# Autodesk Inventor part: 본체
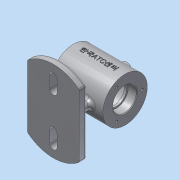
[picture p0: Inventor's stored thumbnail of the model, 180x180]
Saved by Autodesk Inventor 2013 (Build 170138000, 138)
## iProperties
Created: 2017-12
Part Number: 본체
Material: 알루미늄 6061
Document SubType Name: Modeling
Designer: dgall
Density: 2.71 g/cm^3
Mass: 467.692 g
Surface Area: 486.473 cm^2
Volume: 172.58 cm^3
Author: dgall
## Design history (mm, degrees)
sketch "스케치1"
  geometry: L1 (0, 0)-(70, 0); L2 (0, 0)-(0, 30); L3 (0, 30)-(70, 30); L4 (70, 30)-(70, 0)
  constraints: 8 end point, 2 perpendicular, 1 horizontal, 1 parallel
  dimensions: "d0" = 70 distance of L1.start L1.end; "d1" = 60 diameter of L3 L1
revolve "회전1" sketch "스케치1" stored, may be unused: angle "d2" = 90 deg
node "작업 평면1"
sketch "스케치2"
  geometry: L1 (70, -30)-(70, 30) reference; L2 (0, -30)-(0, 30) reference; L3 (0, 30)-(70, 30) reference; L4 (0, -30)-(70, -30) reference; L5 (0, 42.426)-(0, -42.426); L6 (70, 42.426)-(70, -42.426); A1 r 55 centre (35, 0) between (70, 42.426) and (0, 42.426); A2 r 55 centre (35, 0) between (0, -42.426) and (70, -42.426); 3 further points
  constraints: 4 end point, 4 point on circle, 2 centre point, 2 horizontal alignment, 2 midpoint, 1 collinear, 1 concentric, 1 parallel, 1 vertical alignment
  dimensions: "d6" = 70 distance between parallel lines of L6 L5; "d7" = 55 radius of A1
extrude "돌출1" join sketch "스케치2" distance "d8" = 10; taper "d9" = 0 deg
sketch "스케치3"
  geometry: L1 (0, 42.426)-(0, -42.426) reference; L2 (70, -42.426)-(70, 42.426) reference; L3 (20, 5)-(50, 5); L4 (50, -5)-(20, -5); A1 r 55 centre (35, 0) between (0, -42.426) and (70, -42.426) reference; A2 r 5 centre (20, 0) between (20, 5) and (20, -5); A3 r 5 centre (50, 0) between (50, -5) and (50, 5); 4 further points
  constraints: 4 end point, 4 point on circle, 4 vertical alignment, 2 centre point, 2 midpoint, 1 coincident, 1 equal radius, 1 horizontal alignment, 1 parallel, 1 perpendicular
  dimensions: "d13" = 30 distance of A3.centre point (20, 0); "d14" = 5 radius of A3
extrude "돌출2" join sketch "스케치3" stored distance "d15" = 10; taper "d16" = 0 deg
node "작업 평면2"
sketch "스케치4"
  geometry: C1 r 8 at (-35, 0); 1 further point
  constraints: 1 centre point, 1 horizontal alignment
  dimensions: "d18" = 16 diameter of C1; "d20" = 35 distance of point (0, 0) C1.centre
extrude "돌출3" join sketch "스케치4" stored distance "d21" = 10; taper "d22" = 0 deg
hole "구멍1" diameter "d25" = 28; stored, may be unused: countersink angle "d29" = 90 deg, drill point angle "d31" = 0 deg; dims "d23" = 10, "d24" = 10, "d26" = 6, "d27" = 32, "d28" = 12, "d30" = 15
hole "구멍2" diameter "d34" = 28; stored, may be unused: countersink angle "d38" = 90 deg, drill point angle "d40" = 0 deg; dims "d32" = 10, "d33" = 10, "d35" = 6, "d36" = 32, "d37" = 12, "d39" = 15
hole "구멍3" diameter "d43" = 50; stored, may be unused: countersink angle "d47" = 90 deg, drill point angle "d49" = 0 deg; dims "d41" = 10, "d42" = 10, "d44" = 6, "d45" = 32, "d46" = 12, "d48" = 40
hole "구멍4" diameter "d52" = 8; stored, may be unused: countersink angle "d56" = 90 deg, drill point angle "d58" = 0 deg; dims "d50" = 10, "d51" = 10, "d53" = 6, "d54" = 32, "d55" = 12, "d57" = 20
chamfer "모따기1" distance "d59" = 1; stored, may be unused: second distance "d60" = 2, angle "d61" = 45 deg
chamfer "모따기2" distance "d62" = 1; stored, may be unused: second distance "d63" = 2, angle "d64" = 45 deg
fillet "모깎기1" dims "d65" = 0.3
fillet "모깎기2" dims "d66" = 3
sketch "스케치5"
  geometry: L1 (40, 40)-(40, 24); L2 (30, 24)-(30, 40); A1 r 55 centre (35, 0) between (0, -42.426) and (70, -42.426) reference; A2 r 5 centre (50, 0) between (50, -5) and (50, 5) reference; A3 r 5 centre (35, 24) between (30, 24) and (40, 24); A4 r 5 centre (35, 40) between (40, 40) and (30, 40); 3 further points
  constraints: 4 end point, 4 point on circle, 3 horizontal alignment, 2 centre point, 2 coincident, 2 parallel, 2 vertical alignment
  dimensions: "d67" = 5 radius of A4; "d69" = 16 distance of point (35, 24) point (35, 40); "d70" = 24 vertical distance of point (35, 24) A2.centre
extrude "돌출4" cut sketch "스케치5" stored distance "d71" = 10; taper "d72" = 0 deg
node "작업 평면3"
sketch "스케치6"
  geometry: L1 (-35, 30)-(35, 30) reference; L2 (-35, -30)-(-35, 30) reference; 2 further points
  constraints: 1 other
  dimensions: "d73" = 35 distance of point (-35, 0) point (0, 0); "d74" = 30 distance from line of L1 point (0, 0)
feature "엠보싱1" sketch "스케치6" dims "d0" = 70, "d1" = 60, "d75" = 0.5, "d76" = 0
sketch "스케치7"
  geometry: C1 r 30 at (0, 0) reference; 1 further point
  constraints: 1 vertical alignment
  dimensions: "d77" = 23 distance of C1.centre point (0, 23)
hole "구멍5" sketch "스케치7" at (0, 23) diameter "d78" = 3.242; stored, may be unused: countersink angle "d82" = 90 deg, drill point angle "d84" = 118 deg; dims "d79" = 8, "d80" = 32, "d81" = 12, "d83" = 10
node "작업 평면4"
fillet "모깎기3" dims "d88" = 5
fillet "모깎기4" dims "d89" = 3
fillet "모깎기5" dims "d90" = 3
fillet "모깎기6" dims "d91" = 3
node "솔리드1"
mirror "대칭1"
pattern_circular "원형 패턴1" dims angle "d86" = 360 deg
mirror "대칭2"
node "투영된 루프1"
other parameters: "d3" = -62, "d17" = 37
